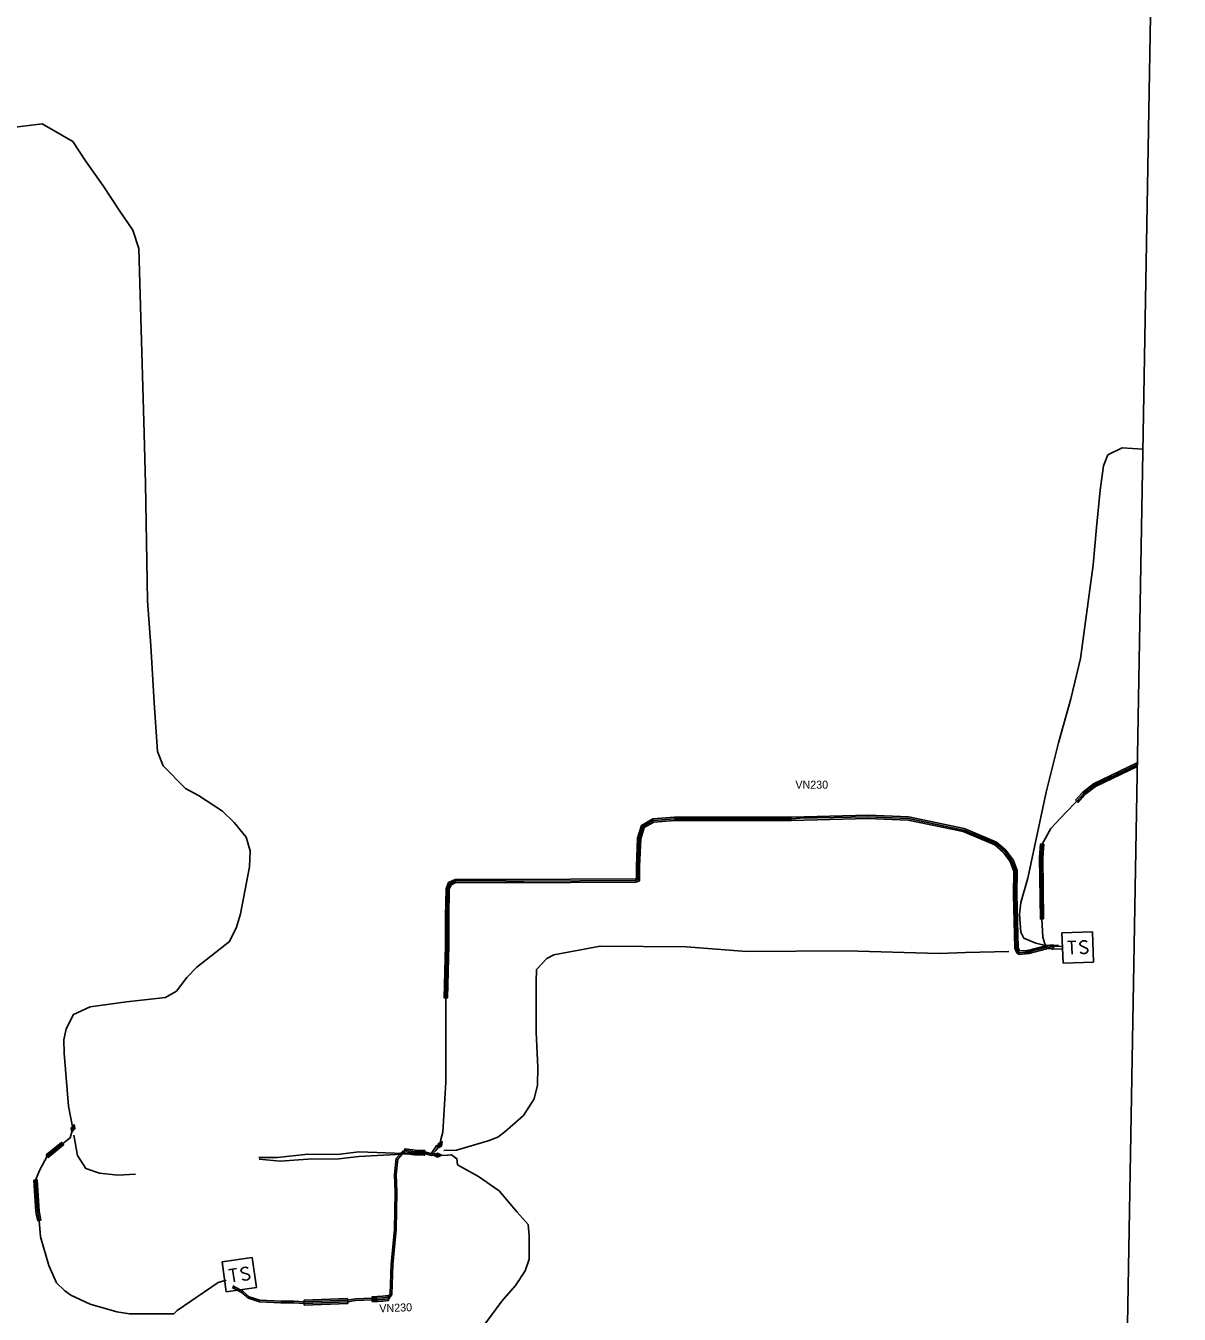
# Model space of a CAD drawing. Extents: x -641829 to -641525, y -1114855 to -1114359.
# Drawn here: x -641668.7 to -641525.3, y -1114723.6 to -1114563.5 of the extents above; entities that cross this region are included whole.
import ezdxf

# ---------------------------------------------------------------- set-up
doc = ezdxf.new("R2010")
doc.units = 0
for name, color, linetype in [('19', 7, 'Continuous'), ('20', 7, 'Continuous'), ('25', 7, 'Continuous'), ('5', 7, 'Continuous'), ('7', 7, 'Continuous'), ('9', 7, 'Continuous'), ('Vrstva 1', 7, 'Continuous')]:
    doc.layers.add(name, color=color, linetype=linetype)

# ---------------------------------------------------------------- blocks, each defined once
blk = doc.blocks.new('VN870')
at = {"layer": '19'}
for points in [[(0, -0.25), (0.5, 0), (0, 0.25), (-0.5, 0), (0, -0.25)], [(0.37, 0), (0, 0.19), (-0.36, 0), (0, -0.19), (0.37, 0)], [(0.24, 0), (0, 0.12), (-0.25, 0), (0, -0.12), (0.24, 0)], [(0.12, 0), (0, 0.06), (-0.13, 0), (0, -0.06), (0.12, 0)]]:
    blk.add_lwpolyline(points, dxfattribs=at)
blk = doc.blocks.new('VN640')
at = {"layer": '25'}
for points in [[(-1.89, 1.89), (1.89, 1.89)], [(-1.89, -1.89), (-1.89, 1.89)], [(1.89, 1.89), (1.89, -1.89)], [(-1.26, 0.79), (-0.22, 0.79)], [(-0.73, 0.79), (-0.73, -0.79)], [(1.2, 0.66), (0.94, 0.79), (0.66, 0.79), (0.41, 0.66), (0.28, 0.47), (0.28, 0.41), (0.41, 0.22), (1.13, -0.16), (1.26, -0.32), (1.26, -0.47), (1.13, -0.66), (0.91, -0.79), (0.63, -0.79), (0.5, -0.73), (0.28, -0.6)], [(1.89, -1.89), (-1.89, -1.89)]]:
    blk.add_lwpolyline(points, dxfattribs=at)

msp = doc.modelspace()

# ---------------------------------------------------------------- linework, layer by layer
at = {"layer": '20'}
for p, q in [((-641530.51, -1114655.07), (-641535.94, -1114657.68)), ((-641535.72, -1114658.02), (-641530.51, -1114655.52)), ((-641530.51, -1114655.52), (-641530.51, -1114655.07)), ((-641535.94, -1114657.68), (-641537.34, -1114658.75)), ((-641537.34, -1114658.75), (-641538.19, -1114659.71)), ((-641537.89, -1114659.97), (-641537.06, -1114659.05)), ((-641537.06, -1114659.05), (-641535.72, -1114658.02)), ((-641538.19, -1114659.71), (-641537.89, -1114659.97))]:
    msp.add_line(p, q, dxfattribs=at)
for points in [[(-641544.04, -1114678.76), (-641544.08, -1114678.36), (-641545.1, -1114678.44), (-641545.17, -1114678.4), (-641545.33, -1114678.02), (-641545.49, -1114671.42), (-641545.45, -1114668.43), (-641545.95, -1114667.12), (-641546.89, -1114665.87), (-641548, -1114664.9), (-641552.04, -1114663.23), (-641558.94, -1114661.78), (-641563.98, -1114661.58), (-641573.49, -1114661.81), (-641588.04, -1114661.83), (-641590.74, -1114662.02), (-641592.14, -1114662.84), (-641592.64, -1114664.41), (-641592.77, -1114667.89), (-641592.78, -1114669.43), (-641592.94, -1114669.49), (-641609, -1114669.56), (-641615.3, -1114669.54), (-641616.13, -1114669.94), (-641616.43, -1114670.66), (-641616.51, -1114674.18), (-641616.49, -1114677.76), (-641616.67, -1114684.26), (-641616.27, -1114684.28), (-641616.09, -1114677.76), (-641616.11, -1114674.18), (-641616.03, -1114670.74), (-641615.82, -1114670.24), (-641615.2, -1114669.94), (-641609, -1114669.96), (-641592.86, -1114669.89), (-641592.38, -1114669.71), (-641592.37, -1114667.89), (-641592.24, -1114664.49), (-641591.8, -1114663.1), (-641590.62, -1114662.42), (-641588.02, -1114662.23), (-641573.49, -1114662.21), (-641563.98, -1114661.98), (-641559, -1114662.18), (-641552.16, -1114663.61), (-641548.22, -1114665.24), (-641547.19, -1114666.15), (-641546.31, -1114667.32), (-641545.85, -1114668.51), (-641545.89, -1114671.42), (-641545.73, -1114678.1), (-641545.49, -1114678.66), (-641545.2, -1114678.86)], [(-641542.16, -1114674.46), (-641542.25, -1114666.81), (-641542.14, -1114665.17), (-641542.54, -1114665.15), (-641542.65, -1114666.81), (-641542.56, -1114674.46)], [(-641541.79, -1114678.16), (-641541.89, -1114677.78), (-641544.11, -1114678.37), (-641544.01, -1114678.75)], [(-641541.82, -1114678.17), (-641540.91, -1114678.09), (-641540.95, -1114677.69), (-641541.86, -1114677.77)], [(-641666.13, -1114703.78), (-641665.88, -1114704.09), (-641663.97, -1114702.53), (-641664.22, -1114702.22)], [(-641619.09, -1114703.21), (-641620.29, -1114703.18), (-641621.55, -1114703.01), (-641621.63, -1114703.61), (-641620.34, -1114703.78), (-641619.1, -1114703.81)], [(-641667.19, -1114711.95), (-641666.8, -1114711.87), (-641666.94, -1114711.22), (-641667.03, -1114710.75), (-641667.26, -1114706.9), (-641667.66, -1114706.92), (-641667.43, -1114710.8), (-641667.33, -1114711.3)], [(-641628.67, -1114721.63), (-641634.08, -1114721.83), (-641634.06, -1114722.43), (-641628.65, -1114722.23)], [(-641623.64, -1114721.25), (-641624.33, -1114721.33), (-641624.99, -1114721.37), (-641625.62, -1114721.39), (-641625.6, -1114721.99), (-641624.96, -1114721.97), (-641624.28, -1114721.93), (-641623.57, -1114721.85)]]:
    msp.add_lwpolyline(points, close=True, dxfattribs=at)
at = {"layer": '5'}
for points in [[(-641662.81, -1114700.48), (-641663.36, -1114697.7), (-641663.89, -1114691.12), (-641663.93, -1114689.46), (-641663.66, -1114688.12), (-641662.73, -1114686.32), (-641660.69, -1114685.36), (-641656.16, -1114684.77), (-641651.29, -1114684.22), (-641649.95, -1114683.45), (-641648.65, -1114681.75), (-641647.42, -1114680.43), (-641643.35, -1114677.27), (-641642.5, -1114675.49), (-641641.97, -1114673.82), (-641640.87, -1114668), (-641640.8, -1114666), (-641641.29, -1114664.31), (-641642.79, -1114662.49), (-641644.22, -1114661.07), (-641647.21, -1114659.12), (-641648.81, -1114658.27), (-641651.58, -1114655.45), (-641652.29, -1114653.67), (-641652.71, -1114647.56), (-641653.14, -1114640.51), (-641653.55, -1114634.92), (-641653.66, -1114627.6), (-641653.79, -1114620.45), (-641653.96, -1114614.09), (-641654.63, -1114591.15), (-641655.36, -1114588.86), (-641656.98, -1114586.52), (-641659.05, -1114583.36), (-641661.24, -1114580.26), (-641662.81, -1114577.88), (-641666.64, -1114575.67), (-641670.67, -1114576.17)], [(-641539.83, -1114678.16), (-641541.04, -1114678.2), (-641541.51, -1114678.05), (-641542, -1114677.56), (-641542.27, -1114676.74), (-641542.36, -1114674.46), (-641542.45, -1114666.82), (-641542.34, -1114665.16), (-641541.25, -1114663.21), (-641539.49, -1114661.33), (-641538.04, -1114659.84), (-641537.2, -1114658.9), (-641535.83, -1114657.85), (-641530.51, -1114655.29)], [(-641539.86, -1114677.84), (-641540.93, -1114677.89), (-641541.84, -1114677.97), (-641544.06, -1114678.56), (-641545.15, -1114678.65), (-641545.33, -1114678.53), (-641545.53, -1114678.06), (-641545.69, -1114671.42), (-641545.65, -1114668.47), (-641546.13, -1114667.22), (-641547.04, -1114666.01), (-641548.11, -1114665.07), (-641552.1, -1114663.42), (-641558.97, -1114661.98), (-641563.98, -1114661.78), (-641572.41, -1114661.95), (-641573.49, -1114662.01), (-641588.03, -1114662.03), (-641590.68, -1114662.22), (-641591.97, -1114662.97), (-641592.44, -1114664.45), (-641592.57, -1114667.89), (-641592.58, -1114669.13), (-641592.58, -1114669.57), (-641592.9, -1114669.69), (-641606.77, -1114669.75), (-641609, -1114669.76), (-641615.25, -1114669.74), (-641615.97, -1114670.09), (-641616.23, -1114670.7), (-641616.31, -1114674.18), (-641616.29, -1114677.76), (-641616.47, -1114684.27), (-641616.48, -1114694.73), (-641616.83, -1114700.96), (-641617.08, -1114701.87), (-641617.21, -1114702.54)], [(-641662.81, -1114700.48), (-641663.16, -1114701.66), (-641664.1, -1114702.38), (-641666.01, -1114703.94), (-641666.93, -1114705.62), (-641667.46, -1114706.91), (-641667.23, -1114710.78), (-641667.14, -1114711.26), (-641667, -1114711.91), (-641666.85, -1114713.94), (-641665.81, -1114717.51), (-641664.87, -1114719.69), (-641663.81, -1114720.67), (-641663.09, -1114721.19), (-641660.69, -1114722.32), (-641657.34, -1114723.28), (-641655.79, -1114723.51), (-641650.27, -1114723.52), (-641649.86, -1114723.09), (-641644.75, -1114719.62), (-641643.76, -1114719.34)], [(-641617.21, -1114702.54), (-641617.69, -1114703.24), (-641618.13, -1114703.67), (-641618.19, -1114703.65), (-641619.08, -1114703.41), (-641620.31, -1114703.38), (-641621.62, -1114703.2), (-641622.01, -1114703.52), (-641622.64, -1114704.24), (-641622.85, -1114706.2), (-641622.75, -1114708.42), (-641622.84, -1114713.04), (-641623.27, -1114717.39), (-641623.38, -1114721.04), (-641623.66, -1114721.45), (-641624.32, -1114721.53), (-641624.98, -1114721.57), (-641625.61, -1114721.59), (-641627.71, -1114721.67), (-641628.67, -1114721.83), (-641634.07, -1114722.03), (-641635.33, -1114721.96), (-641636.95, -1114721.96), (-641639.6, -1114721.82), (-641640.9, -1114721.39), (-641641.67, -1114720.75), (-641642.94, -1114720.06)], [(-641617.49, -1114703.8), (-641618.24, -1114703.85), (-641619.11, -1114703.61), (-641620.32, -1114703.58), (-641621.56, -1114703.41), (-641621.87, -1114703.66), (-641622.45, -1114704.32), (-641622.65, -1114706.2), (-641622.55, -1114708.42), (-641622.64, -1114713.05), (-641623.07, -1114717.41), (-641623.18, -1114721.1), (-641623.55, -1114721.64), (-641624.3, -1114721.73), (-641624.97, -1114721.77), (-641625.6, -1114721.79), (-641627.69, -1114721.87), (-641628.65, -1114722.03), (-641634.07, -1114722.23), (-641635.34, -1114722.16), (-641636.96, -1114722.16), (-641639.64, -1114722.02), (-641641, -1114721.57), (-641641.78, -1114720.91), (-641643.03, -1114720.24)], [(-641617.49, -1114703.8), (-641616.76, -1114703.83), (-641615.76, -1114703.75), (-641615.09, -1114704.25), (-641615, -1114704.99), (-641612.4, -1114706.46), (-641609.82, -1114708.25), (-641607.61, -1114710.88), (-641606.23, -1114712.44), (-641606.09, -1114713.81), (-641606.09, -1114716.75), (-641606.6, -1114718.16), (-641607.82, -1114719.99), (-641609.52, -1114721.95), (-641611.62, -1114724.81)]]:
    msp.add_lwpolyline(points, dxfattribs=at)
at = {"layer": '9'}
for points in [[(-641529.81, -1114616.08), (-641532.38, -1114615.94), (-641534.16, -1114616.81), (-641534.71, -1114618.17), (-641535.12, -1114621.18), (-641535.57, -1114625.81), (-641535.98, -1114630.44), (-641537.57, -1114642.09), (-641538.78, -1114647.13), (-641540.32, -1114652.58), (-641541.86, -1114658.7), (-641543.31, -1114665.49), (-641544.1, -1114669.41), (-641545.01, -1114672.43), (-641545.15, -1114673.86), (-641544.99, -1114676.12), (-641544.6, -1114676.86), (-641543.14, -1114677.48), (-641541.94, -1114677.77), (-641540.29, -1114677.7)], [(-641546.49, -1114678.5), (-641551.87, -1114678.63), (-641555.13, -1114678.76), (-641566.7, -1114678.43), (-641579.1, -1114678.51), (-641586.54, -1114677.92), (-641597.28, -1114677.84), (-641603.05, -1114678.91), (-641603.91, -1114679.38), (-641605.21, -1114680.75), (-641605.22, -1114682.27), (-641605.22, -1114688.51), (-641605.03, -1114692.88), (-641605.06, -1114695.13), (-641605.48, -1114696.8), (-641606.79, -1114698.87), (-641609.15, -1114700.91), (-641610, -1114701.56), (-641611.22, -1114702.04), (-641615.13, -1114703.17), (-641616.73, -1114703.22)], [(-641655.04, -1114706.17), (-641657.25, -1114706.3), (-641659.51, -1114706.04), (-641661.22, -1114705.47), (-641662.25, -1114703.83), (-641662.7, -1114701.34)], [(-641617.57, -1114702.57), (-641618.24, -1114703.56), (-641619.48, -1114703.68), (-641627.28, -1114703.39), (-641629.91, -1114703.71), (-641633.62, -1114703.69), (-641637.37, -1114704.1), (-641639.7, -1114704.11)], [(-641639.68, -1114704.31), (-641637.04, -1114704.57), (-641633.63, -1114704.31), (-641629.76, -1114704.27), (-641627.29, -1114703.96), (-641619.58, -1114703.57), (-641617.86, -1114703.65)]]:
    msp.add_lwpolyline(points, dxfattribs=at)
at = {"layer": 'Vrstva 1'}
msp.add_line((-641533.66, -1114832.21), (-641525.3, -1114362.64), dxfattribs=at)

# ---------------------------------------------------------------- block references
at = {"layer": '19'}
for p, rotation in [((-641544.06, -1114678.56), 14.999999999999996), ((-641662.81, -1114700.48), -106.00000000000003), ((-641617.21, -1114702.54), -124.00000000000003), ((-641617.49, -1114703.8), -1.9999999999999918)]:
    msp.add_blockref('VN870', p, dxfattribs=dict(at, rotation=rotation))
at = {"layer": '25'}
for p, rotation in [((-641537.92, -1114678), 2), ((-641642.14, -1114718.65), 8)]:
    msp.add_blockref('VN640', p, dxfattribs=dict(at, rotation=rotation))

# ---------------------------------------------------------------- texts
at = {"layer": '7'}
for rotation, p in [(0.0788, (-641573.01, -1114658.28)), (2.1172, (-641624.71, -1114723.34))]:
    msp.add_text('VN230', height=0.994, rotation=rotation, dxfattribs=at).set_placement(p)

doc.saveas('drawing.dxf')
